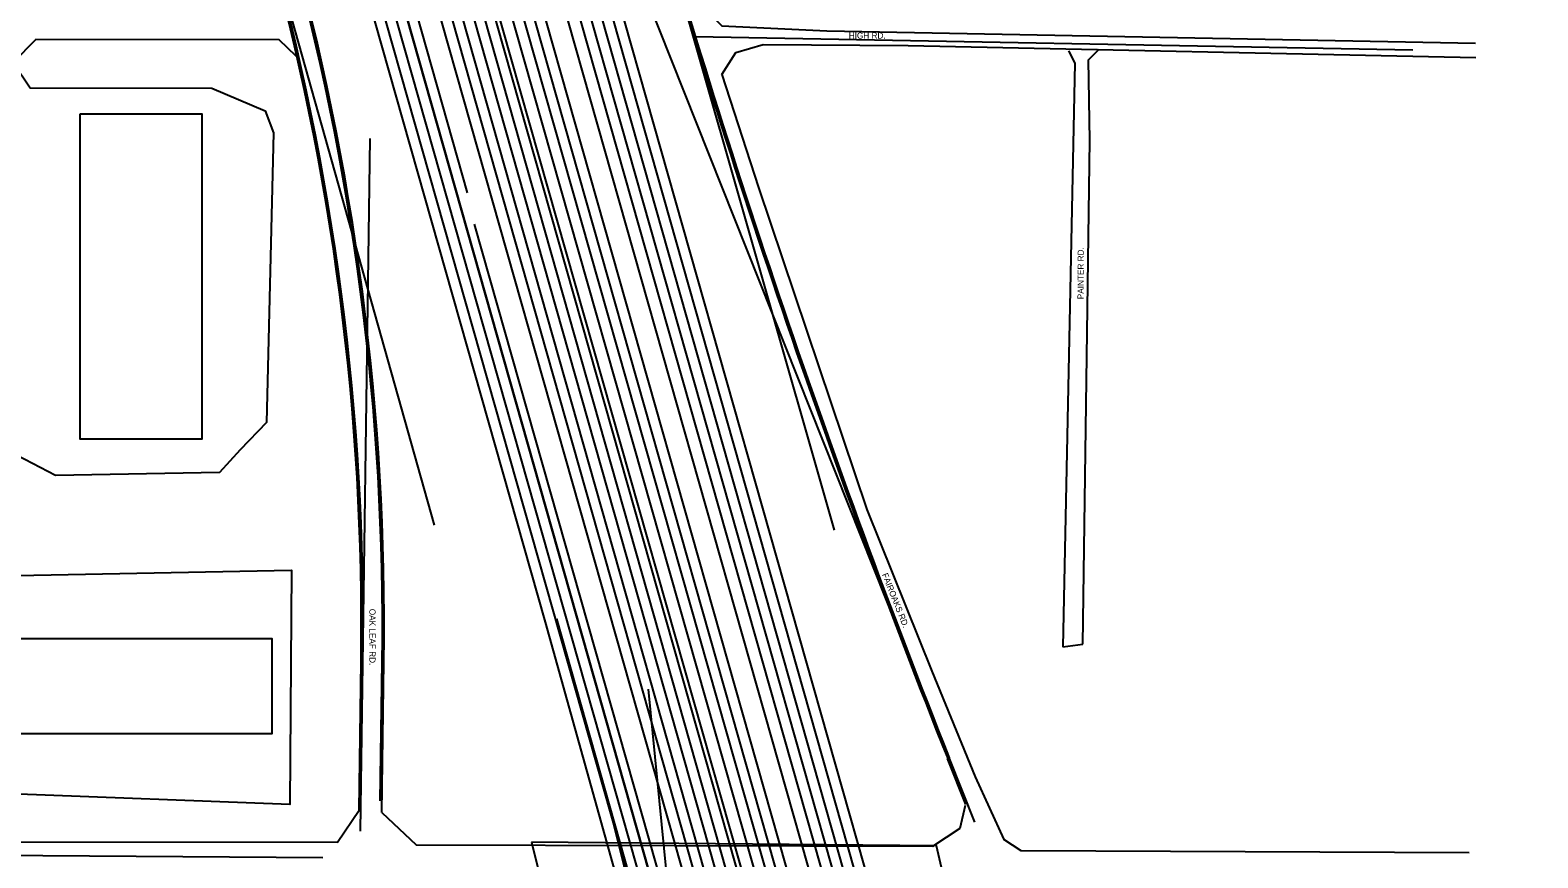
# Model space of a CAD drawing. Extents: x 227157 to 233208, y 434992 to 456232.
# Drawn here: x 228022 to 229741, y 440241 to 441185 of the extents above; entities that cross this region are included whole.
import ezdxf

# ---------------------------------------------------------------- set-up
doc = ezdxf.new("R2010")
doc.units = 0
for name, color, linetype in [('BD_X_Building', 7, 'Continuous'), ('BR_X_Slab_Object', 7, 'Continuous'), ('GE_X_Alignment', 7, 'Continuous'), ('PM_X_Edge_Line', 7, 'Continuous'), ('PM_X_Lane_Line', 7, 'Continuous'), ('PV_X_EOP', 7, 'Continuous'), ('SV_X_Text_Name', 7, 'Continuous')]:
    doc.layers.add(name, color=color, linetype=linetype)

msp = doc.modelspace()

# ---------------------------------------------------------------- linework, layer by layer
at = {"layer": 'BD_X_Building'}
for points in [[(228079.2, 441089.4), (228217.7, 441089.4), (228217.7, 440718.6), (228079.2, 440718.6)], [(227983.1, 440491.4), (228297.6, 440491.4), (228297.6, 440382.7), (227983.1, 440382.7)]]:
    msp.add_lwpolyline(points, close=True, dxfattribs=at)
at = {"layer": 'BR_X_Slab_Object'}
msp.add_lwpolyline([(228593.7, 440259.3), (228612.3, 440184.5), (229072.1, 440182.7), (229055.3, 440255.1)], close=True, dxfattribs=at)
at = {"layer": 'GE_X_Alignment'}
for p, q in [((229741.1, 437351.7), (227977.9, 443563.5)), ((229633.3, 437464.5), (227927.6, 443466.1)), ((227851.2, 443315.4), (228989, 439305.6)), ((229609.5, 437429.5), (227988.9, 443142.3)), ((228939, 440614.9), (228424.6, 442414.9)), ((228102.1, 441970.7), (228482.9, 440620.6)), ((229099.2, 440282.1), (228634.2, 441450.4)), ((228398.7, 440271.8), (228409.9, 441061.3)), ((228622.4, 440513.9), (228801.2, 439882.3)), ((228919.8, 438478), (228727.1, 440433.7))]:
    msp.add_line(p, q, dxfattribs=at)
for centre, radius, start, end in [((239163.9, 444372.1), 10863.7, 195.95, 201.69969), ((225496.6, 440506.4), 2905.1, 359.1873, 15.7485), ((224290.9, 439141.4), 4541.6, 5.6268, 15.809)]:
    msp.add_arc(centre, radius, start, end, dxfattribs=at)
at = {"layer": 'PM_X_Edge_Line'}
for p, q in [((229405.2, 438534.9), (228394.3, 442096.5)), ((229527.9, 437923.2), (228350.6, 442065.3)), ((229328.7, 438419.5), (228298.5, 442051)), ((229504.8, 437916.6), (228327.5, 442058.8)), ((228263.8, 442041.2), (229294, 438409.6)), ((228766.4, 440002.2), (228193.6, 442020.7)), ((228789.4, 440008.8), (228216.7, 442027.3)), ((229037.1, 439963.6), (228452, 442025.2)), ((228780.4, 441177.7), (229598.7, 441162.4)), ((228660.6, 440378.7), (228622.4, 440513.9)), ((228398.7, 440271.8), (228401.5, 440465.2)), ((228421.2, 440306.6), (228423.5, 440464.9)), ((229099.2, 440282.1), (229070, 440355.3))]:
    msp.add_line(p, q, dxfattribs=at)
for centre, radius, start, end in [((239163.9, 444372.1), 10863.7, 195.95, 201.69969), ((225496.6, 440506.4), 2905.1, 359.1873, 15.7485), ((225496.6, 440506.4), 2927.1, 359.1873, 15.7485), ((224290.9, 439141.4), 4541.6, 5.6268, 15.809)]:
    msp.add_arc(centre, radius, start, end, dxfattribs=at)
at = {"layer": 'PM_X_Lane_Line'}
for p, q in [((229416.8, 438538.2), (228405.8, 442099.8)), ((229047.9, 439881.6), (228417.4, 442103.1)), ((228286.9, 442047.7), (229317.1, 438416.2)), ((228339.1, 442062.1), (229516.3, 437919.9)), ((229305.6, 438412.9), (228275.4, 442044.5)), ((228777.9, 440005.5), (228205.2, 442024)), ((227163.2, 440251), (228355.8, 440241.7))]:
    msp.add_line(p, q, dxfattribs=at)
at = {"layer": 'PV_X_EOP'}
for p, q in [((229391.8, 438531.1), (228380.8, 442092.7)), ((229539.4, 437926.5), (228362.2, 442068.6)), ((229340.2, 438422.7), (228310, 442054.3)), ((229391.7, 438263.5), (228314.1, 442054.9)), ((228520.8, 440999.5), (228228.2, 442030.6)), ((229282.5, 438406.4), (228252.3, 442037.9)), ((229080.9, 439853.3), (228458.9, 442044.8)), ((228609.7, 440510.2), (228182.1, 442017.5)), ((228799.1, 440011.5), (228528.9, 440963.7)), ((228702.7, 440176.3), (228609.7, 440510.2)), ((229199.5, 440481.9), (229222.2, 440485.2)), ((228397.1, 440295.8), (228399.5, 440465.3)), ((228423, 440293.3), (228425.5, 440464.9)), ((229089, 440302.3), (229068.2, 440354.6)), ((229082.3, 440275.3), (229088.5, 440301.7))]:
    msp.add_line(p, q, dxfattribs=at)
for points in [[(228793.5, 441206.7), (228810.7, 441189.8), (228930.5, 441184.1), (229670.1, 441170)], [(228325.4, 441155.3), (228306.2, 441174), (228028.6, 441174.2), (228002.9, 441148.1), (228022, 441119.1), (228229.3, 441118.7), (228290, 441092.8), (228299.4, 441068), (228291.6, 440737.8), (228261.4, 440706.4), (228238.1, 440680.9), (228051.2, 440677.4), (227989.9, 440709.1), (227950.6, 440837.1), (227965.8, 441152.9), (227943.8, 441174.5)], [(228810.9, 441134.5), (228826.7, 441159.5), (228858, 441168.7), (229023, 441167.6), (229670.2, 441153.7)], [(229206.1, 441161.2), (229213.3, 441147.2), (229199.5, 440481.9)], [(229222.2, 440485.2), (229230.4, 441059.2), (229228.7, 441151.2), (229241, 441163.4)], [(228810.9, 441134.5), (228852.6, 441005.7), (228976, 440638.7), (229050.2, 440454.4), (229099.4, 440333.9), (229132.1, 440262.4)], [(227989.9, 440709.1), (227986.8, 440563), (228320.1, 440569.3), (228318.1, 440302.2), (227999.3, 440314.5), (228001.9, 440259.6)], [(228001.9, 440259.6), (228372.6, 440259.4), (228397.1, 440295.8)], [(228423, 440293.3), (228462.4, 440256.2), (229051.4, 440254.7), (229082.3, 440275.3)], [(229662.9, 440247.2), (229151.9, 440249.5), (229132.1, 440262.4)]]:
    msp.add_lwpolyline(points, dxfattribs=at)
for centre, radius, start, end in [((239163.9, 444372.1), 10865.7, 195.95, 201.69969), ((225496.6, 440506.4), 2903.1, 359.1873, 15.7485), ((225496.6, 440506.4), 2929.1, 359.1873, 15.7485)]:
    msp.add_arc(centre, radius, start, end, dxfattribs=at)

# ---------------------------------------------------------------- texts
at = {"layer": 'SV_X_Text_Name'}
msp.add_text('HIGH RD.', height=7, dxfattribs=at).set_placement((228955.4, 441175.3))
for s, rotation, p in [('PAINTER RD.', 89.8081, (229223.2, 440878.2)), ('FAIROAKS RD.', 291.7724, (228993.2, 440564.4)), ('OAK LEAF RD.', 270, (228408.9, 440525.4))]:
    msp.add_text(s, height=7, rotation=rotation, dxfattribs=at).set_placement(p)

doc.saveas('drawing.dxf')
